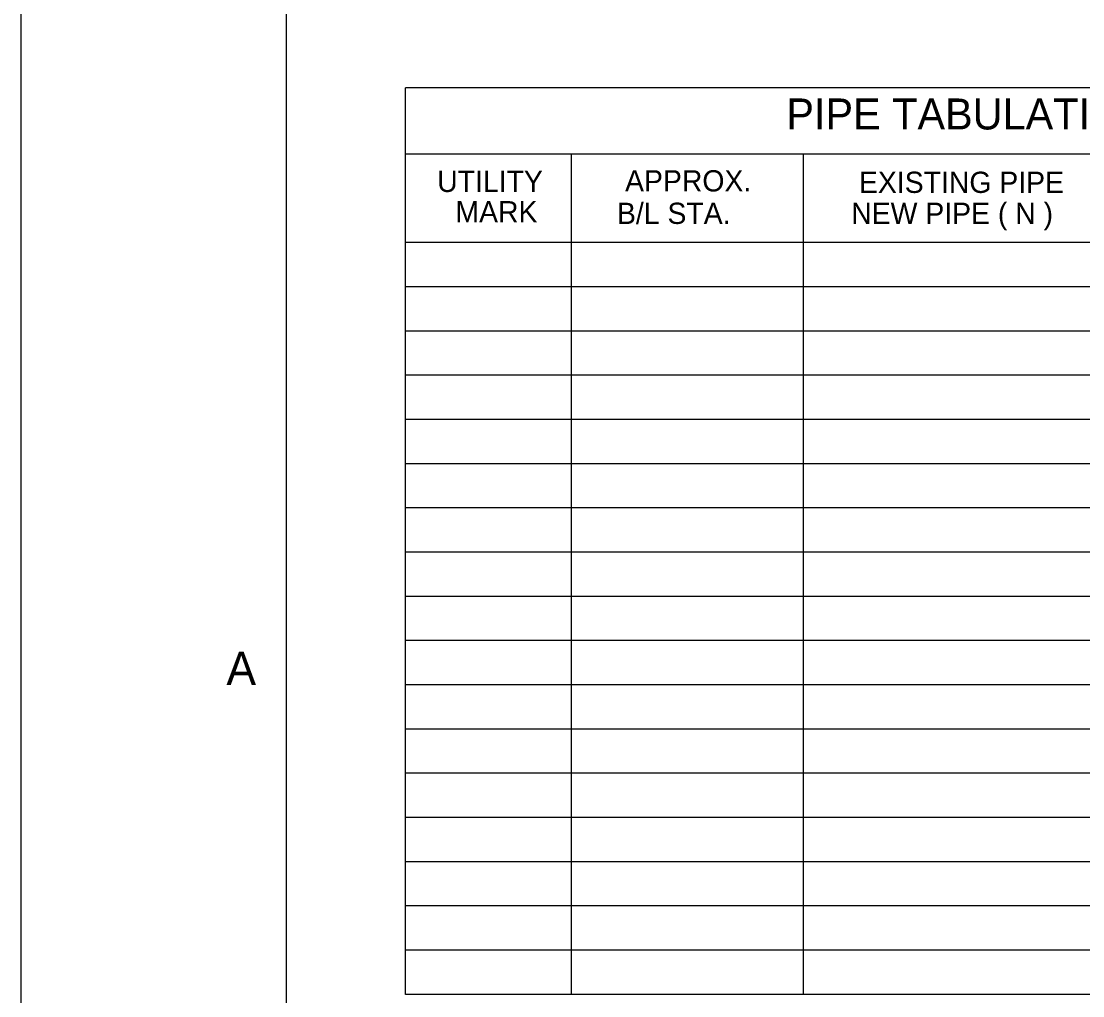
# Model space of a CAD drawing. Extents: x 22339.2 to 22413.4, y 22369.6 to 22418.8.
# Drawn here: x 22354.72 to 22362.72, y 22373.31 to 22380.66 of the extents above; entities that cross this region are included whole.
import ezdxf

# ---------------------------------------------------------------- set-up
doc = ezdxf.new("R2010")
doc.units = 0
for name, color, linetype in [('Level 1', 7, 'Continuous'), ('Level 2', 7, 'Continuous'), ('Level 4', 7, 'Continuous'), ('Level 7', 7, 'Continuous'), ('Level 9', 7, 'Continuous')]:
    doc.layers.add(name, color=color, linetype=linetype)

msp = doc.modelspace()

# ---------------------------------------------------------------- linework, layer by layer
at = {"layer": 'Level 1'}
msp.add_lwpolyline([(22354.7191, 22414.9653), (22413.3862, 22414.9653), (22413.3862, 22369.6213), (22354.7191, 22369.6213)], close=True, dxfattribs=at)
at = {"layer": 'Level 2'}
for p, q in [((22369.367, 22378.6537), (22357.617, 22378.6537)), ((22369.367, 22378.3204), (22357.617, 22378.3204)), ((22369.367, 22377.9871), (22357.617, 22377.9871)), ((22369.367, 22377.6537), (22357.617, 22377.6537)), ((22369.367, 22377.3204), (22357.617, 22377.3204)), ((22369.367, 22376.9871), (22357.617, 22376.9871)), ((22369.367, 22376.6537), (22357.617, 22376.6537)), ((22369.367, 22376.3204), (22357.617, 22376.3204)), ((22369.367, 22375.9871), (22357.617, 22375.9871)), ((22369.367, 22375.6537), (22357.617, 22375.6537)), ((22369.367, 22375.3204), (22357.617, 22375.3204)), ((22369.367, 22374.9871), (22357.617, 22374.9871)), ((22369.367, 22374.6537), (22357.617, 22374.6537)), ((22369.367, 22374.3204), (22357.617, 22374.3204)), ((22369.367, 22373.9871), (22357.617, 22373.9871)), ((22369.367, 22373.6537), (22357.617, 22373.6537))]:
    msp.add_line(p, q, dxfattribs=at)
at = {"layer": 'Level 7'}
for p, q in [((22369.367, 22380.1537), (22357.617, 22380.1537)), ((22357.617, 22373.3204), (22357.617, 22380.1537)), ((22369.367, 22379.6537), (22357.617, 22379.6537)), ((22358.867, 22373.3204), (22358.867, 22379.6537)), ((22360.617, 22373.3204), (22360.617, 22379.6537)), ((22369.367, 22378.9871), (22357.617, 22378.9871)), ((22369.367, 22373.3204), (22357.617, 22373.3204))]:
    msp.add_line(p, q, dxfattribs=at)
at = {"layer": 'Level 9'}
msp.add_line((22356.7191, 22370.2933), (22356.7191, 22414.2933), dxfattribs=at)

# ---------------------------------------------------------------- texts
at = {"layer": 'Level 1'}
msp.add_text('A', height=0.2497, dxfattribs=at).set_placement((22356.2662, 22375.6533))
at = {"layer": 'Level 4'}
for s, height, p in [('PIPE TABULATION AND SLEEVE TABLE', 0.233333, (22360.487, 22379.8398)), ('UTILITY', 0.16, (22357.8546, 22379.3685)), ('APPROX.', 0.16, (22359.271, 22379.3726)), ('EXISTING PIPE', 0.16, (22361.0341, 22379.3614)), ('MARK', 0.16, (22357.9923, 22379.1395)), ('B/L STA.', 0.16, (22359.21, 22379.1276)), ('NEW PIPE ( N )', 0.16, (22360.9758, 22379.1277))]:
    msp.add_text(s, height=height, dxfattribs=at).set_placement(p)

doc.saveas('drawing.dxf')
